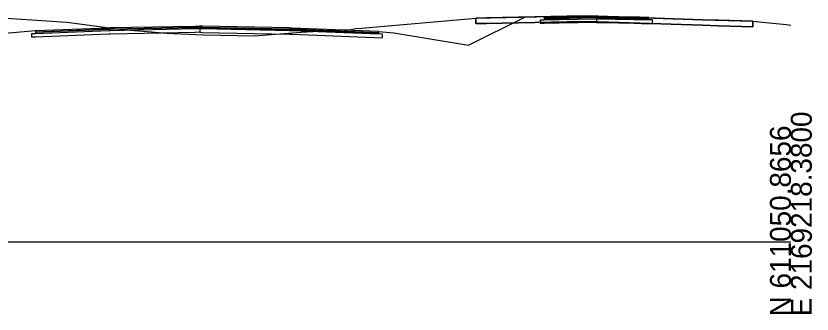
# Model space of a CAD drawing. Extents: x -26 to 1303, y -3010 to 12038.
# Drawn here: x 1196.2 to 1302.8, y 6990.3 to 7030.3 of the extents above; entities that cross this region are included whole.
import ezdxf

# ---------------------------------------------------------------- set-up
doc = ezdxf.new("R2010")
doc.units = 0
for name, color, linetype in [('RD_GPK_XS_Cell', 7, 'Continuous'), ('RD_XS_Base', 7, 'Continuous'), ('RD_XS_ExGround', 7, 'Continuous'), ('RD_XS_ExPaveRet', 7, 'Continuous'), ('RD_XS_Greenside', 7, 'Continuous'), ('RD_XS_Pave', 7, 'Continuous'), ('RD_XS_PaveOvlay_CP', 7, 'Continuous'), ('RD_XS_TieSlope', 7, 'Continuous')]:
    doc.layers.add(name, color=color, linetype=linetype)

msp = doc.modelspace()

# ---------------------------------------------------------------- linework, layer by layer
at = {"layer": 'RD_GPK_XS_Cell'}
msp.add_line((1150, 7000), (1300, 7000), dxfattribs=at)
at = {"layer": 'RD_XS_Base'}
for p, q in [((1266.47, 7029.77), (1266.97, 7029.78)), ((1266.47, 7029.27), (1266.47, 7029.77)), ((1266.97, 7029.78), (1268.97, 7029.82)), ((1268.97, 7029.82), (1273.97, 7029.92)), ((1273.97, 7029.42), (1268.97, 7029.32)), ((1273.97, 7029.99), (1273.97, 7030.08)), ((1273.97, 7030.08), (1273.97, 7029.7)), ((1273.97, 7029.92), (1273.97, 7029.99)), ((1276.91, 7029.86), (1273.97, 7029.92)), ((1273.97, 7029.92), (1273.97, 7029.42)), ((1273.97, 7029.7), (1273.97, 7029.42)), ((1273.97, 7029.42), (1276.91, 7029.36)), ((1278.97, 7029.82), (1276.91, 7029.86)), ((1279.78, 7029.8), (1278.97, 7029.82)), ((1280.97, 7029.78), (1279.78, 7029.8)), ((1281.17, 7029.77), (1280.97, 7029.78)), ((1281.47, 7029.77), (1281.17, 7029.77)), ((1281.47, 7029.47), (1281.47, 7029.77)), ((1281.47, 7029.27), (1281.47, 7029.47)), ((1198.81, 7027.97), (1208.65, 7028.36)), ((1208.65, 7028.36), (1208.81, 7028.37)), ((1208.81, 7028.37), (1220.21, 7028.6)), ((1220.21, 7028.6), (1220.81, 7028.61)), ((1220.81, 7028.76), (1220.81, 7028.77)), ((1220.81, 7028.77), (1220.81, 7028.75)), ((1220.81, 7028.61), (1220.81, 7028.76)), ((1220.81, 7028.75), (1220.81, 7028.11)), ((1220.81, 7028.61), (1220.81, 7028.6)), ((1220.81, 7028.61), (1220.81, 7028.61)), ((1221.12, 7028.6), (1220.81, 7028.61)), ((1220.81, 7028.61), (1220.81, 7028.61)), ((1220.81, 7028.6), (1220.81, 7028.11)), ((1232.81, 7028.37), (1221.12, 7028.6)), ((1233.17, 7028.35), (1232.81, 7028.37)), ((1244.81, 7027.89), (1233.17, 7028.35)), ((1266.97, 7029.28), (1266.47, 7029.27)), ((1268.97, 7029.32), (1266.97, 7029.28)), ((1276.91, 7029.36), (1278.97, 7029.32)), ((1278.97, 7029.32), (1279.98, 7029.3)), ((1279.98, 7029.3), (1281.47, 7029.27)), ((1198.31, 7027.95), (1198.81, 7027.97)), ((1198.31, 7027.94), (1198.31, 7027.95)), ((1198.31, 7027.45), (1198.31, 7027.94)), ((1198.81, 7027.47), (1198.31, 7027.45)), ((1198.81, 7027.97), (1198.81, 7027.97)), ((1208.65, 7027.86), (1198.81, 7027.47)), ((1198.81, 7027.47), (1198.81, 7027.47)), ((1208.81, 7027.87), (1208.65, 7027.86)), ((1220.21, 7028.1), (1208.81, 7027.87)), ((1220.81, 7028.11), (1220.21, 7028.1)), ((1220.81, 7028.11), (1221.12, 7028.1)), ((1221.12, 7028.1), (1232.81, 7027.87)), ((1232.81, 7027.87), (1233.19, 7027.85)), ((1233.19, 7027.85), (1245.31, 7027.37)), ((1244.83, 7027.89), (1244.81, 7027.89)), ((1245.31, 7027.87), (1244.83, 7027.89)), ((1245.31, 7027.85), (1245.31, 7027.87)), ((1245.31, 7027.37), (1245.31, 7027.85))]:
    msp.add_line(p, q, dxfattribs=at)
at = {"layer": 'RD_XS_ExGround'}
msp.add_lwpolyline([(1193.56, 7030.11), (1201.68, 7029.57), (1202.23, 7029.53), (1203.01, 7029.47), (1208.06, 7028.78), (1210.38, 7028.5), (1214.37, 7028.17), (1216.34, 7028), (1221.28, 7027.76), (1228.11, 7027.65), (1234.4, 7028.15), (1239.78, 7028.45), (1241.04, 7028.5), (1241.72, 7028.6), (1242.48, 7028.65), (1257.79, 7030.02), (1270, 7030.27), (1272.49, 7030.31), (1288.17, 7029.8), (1294.91, 7029.59), (1297.1, 7029.37), (1299.41, 7029.15), (1300, 7029.09)], dxfattribs=at)
at = {"layer": 'RD_XS_ExPaveRet'}
msp.add_line((1259.24, 7030.05), (1257.79, 7030.02), dxfattribs=at)
for points in [[(1294.91, 7029.59), (1294.91, 7029.59), (1294.91, 7029.45), (1294.91, 7028.84), (1294.91, 7028.84), (1294.91, 7028.84), (1290.29, 7028.99), (1288.17, 7029.05), (1274.19, 7029.51), (1272.49, 7029.56), (1270.69, 7029.53), (1270, 7029.52), (1259.24, 7029.3), (1257.79, 7029.27), (1257.79, 7029.92), (1257.79, 7030.02), (1259.24, 7030.05), (1270, 7030.27), (1270.69, 7030.28), (1272.49, 7030.31), (1274.19, 7030.26), (1288.17, 7029.8), (1290.29, 7029.74), (1294.91, 7029.59), (1294.91, 7029.59)], [(1257.79, 7030.02), (1257.79, 7029.92), (1257.79, 7029.27), (1259.24, 7029.3), (1270, 7029.52), (1270.69, 7029.53), (1272.49, 7029.56), (1274.19, 7029.51), (1288.17, 7029.05), (1290.29, 7028.99), (1294.91, 7028.84), (1294.91, 7028.84), (1294.91, 7029.45), (1294.91, 7029.59), (1294.91, 7029.59), (1290.29, 7029.74)], [(1270.69, 7030.28), (1270, 7030.27), (1259.24, 7030.05)], [(1274.19, 7030.26), (1272.49, 7030.31), (1270.69, 7030.28)], [(1290.29, 7029.74), (1288.17, 7029.8), (1274.19, 7030.26)]]:
    msp.add_lwpolyline(points, dxfattribs=at)
at = {"layer": 'RD_XS_Greenside'}
for p, q in [((1256.81, 7026.38), (1264.36, 7030.15)), ((1246.81, 7028.05), (1256.81, 7026.38))]:
    msp.add_line(p, q, dxfattribs=at)
at = {"layer": 'RD_XS_Pave'}
for p, q in [((1267.84, 7030.11), (1266.97, 7030.1)), ((1266.97, 7030.1), (1266.97, 7030.01)), ((1266.97, 7030.01), (1266.97, 7029.94)), ((1268.97, 7029.98), (1266.97, 7029.94)), ((1266.97, 7029.94), (1267.84, 7029.95)), ((1266.97, 7029.94), (1266.97, 7029.78)), ((1266.97, 7029.78), (1268.97, 7029.82)), ((1268.97, 7030.14), (1267.84, 7030.11)), ((1267.84, 7029.95), (1268.97, 7029.98)), ((1271.84, 7030.19), (1268.97, 7030.14)), ((1273.97, 7030.08), (1268.97, 7029.98)), ((1268.97, 7029.98), (1271.84, 7030.03)), ((1268.97, 7029.82), (1273.97, 7029.92)), ((1273.97, 7030.24), (1271.84, 7030.19)), ((1271.84, 7030.03), (1273.97, 7030.08)), ((1276.91, 7030.18), (1273.97, 7030.24)), ((1273.97, 7030.08), (1276.91, 7030.02)), ((1278.97, 7029.98), (1273.97, 7030.08)), ((1273.97, 7030.08), (1273.97, 7029.92)), ((1273.97, 7029.92), (1273.97, 7030.08)), ((1273.97, 7029.92), (1278.97, 7029.82)), ((1278.97, 7030.14), (1276.91, 7030.18)), ((1276.91, 7030.02), (1278.97, 7029.98)), ((1279.78, 7030.12), (1278.97, 7030.14)), ((1278.97, 7029.98), (1279.78, 7029.96)), ((1280.97, 7029.94), (1278.97, 7029.98)), ((1278.97, 7029.82), (1280.97, 7029.78)), ((1280.97, 7030.1), (1279.78, 7030.12)), ((1279.78, 7029.96), (1280.97, 7029.94)), ((1280.97, 7030), (1280.97, 7030.1)), ((1280.97, 7029.94), (1280.97, 7030)), ((1280.97, 7029.78), (1280.97, 7029.94)), ((1208.65, 7028.68), (1198.81, 7028.29)), ((1208.65, 7028.52), (1198.81, 7028.13)), ((1198.81, 7028.13), (1208.65, 7028.52)), ((1198.81, 7027.97), (1208.65, 7028.36)), ((1208.81, 7028.69), (1208.65, 7028.68)), ((1208.81, 7028.53), (1208.65, 7028.52)), ((1208.65, 7028.52), (1208.81, 7028.53)), ((1208.65, 7028.36), (1208.81, 7028.37)), ((1220.21, 7028.91), (1208.81, 7028.69)), ((1220.21, 7028.76), (1208.81, 7028.53)), ((1208.81, 7028.53), (1220.21, 7028.76)), ((1208.81, 7028.37), (1220.21, 7028.6)), ((1220.81, 7028.93), (1220.21, 7028.91)), ((1220.81, 7028.77), (1220.21, 7028.76)), ((1220.21, 7028.76), (1220.81, 7028.77)), ((1220.21, 7028.6), (1220.81, 7028.61)), ((1221.12, 7028.92), (1220.81, 7028.93)), ((1220.81, 7028.76), (1220.81, 7028.77)), ((1220.81, 7028.77), (1221.12, 7028.76)), ((1221.12, 7028.76), (1220.81, 7028.77)), ((1220.81, 7028.77), (1220.81, 7028.77)), ((1220.81, 7028.77), (1220.81, 7028.77)), ((1220.81, 7028.77), (1220.81, 7028.76)), ((1220.81, 7028.61), (1220.81, 7028.76)), ((1220.81, 7028.76), (1220.81, 7028.61)), ((1220.81, 7028.61), (1220.81, 7028.61)), ((1220.81, 7028.61), (1220.81, 7028.61)), ((1220.81, 7028.61), (1221.12, 7028.6)), ((1232.81, 7028.69), (1221.12, 7028.92)), ((1221.12, 7028.76), (1232.81, 7028.53)), ((1232.81, 7028.53), (1221.12, 7028.76)), ((1221.12, 7028.6), (1232.81, 7028.37)), ((1233.17, 7028.67), (1232.81, 7028.69)), ((1232.81, 7028.53), (1233.17, 7028.51)), ((1233.17, 7028.51), (1232.81, 7028.53)), ((1232.81, 7028.37), (1233.17, 7028.35)), ((1244.81, 7028.21), (1233.17, 7028.67)), ((1233.17, 7028.51), (1244.81, 7028.05)), ((1244.81, 7028.05), (1233.17, 7028.51)), ((1233.17, 7028.35), (1244.81, 7027.89)), ((1198.81, 7028.29), (1198.81, 7028.28)), ((1198.81, 7028.28), (1198.81, 7028.13)), ((1198.81, 7028.13), (1198.81, 7028.13)), ((1198.81, 7028.13), (1198.81, 7027.97)), ((1244.81, 7028.2), (1244.81, 7028.21)), ((1244.81, 7028.05), (1244.81, 7028.2)), ((1244.81, 7028.04), (1244.81, 7028.05)), ((1244.81, 7027.89), (1244.81, 7028.04))]:
    msp.add_line(p, q, dxfattribs=at)
at = {"layer": 'RD_XS_PaveOvlay_CP'}
for p, q in [((1266.97, 7030.1), (1268.97, 7030.14)), ((1268.97, 7030.14), (1273.97, 7030.24)), ((1273.97, 7030.24), (1278.97, 7030.14)), ((1278.97, 7030.14), (1280.97, 7030.1)), ((1208.65, 7028.68), (1198.81, 7028.29)), ((1208.81, 7028.69), (1208.65, 7028.68)), ((1220.21, 7028.91), (1208.81, 7028.69)), ((1220.81, 7028.93), (1220.21, 7028.91)), ((1221.12, 7028.92), (1220.81, 7028.93)), ((1232.81, 7028.69), (1221.12, 7028.92)), ((1233.17, 7028.67), (1232.81, 7028.69)), ((1244.81, 7028.21), (1233.17, 7028.67))]:
    msp.add_line(p, q, dxfattribs=at)
at = {"layer": 'RD_XS_TieSlope'}
for p, q in [((1198.81, 7028.29), (1192.81, 7027.81)), ((1244.81, 7028.21), (1246.81, 7028.05))]:
    msp.add_line(p, q, dxfattribs=at)

# ---------------------------------------------------------------- texts
at = {"layer": 'RD_GPK_XS_Cell'}
for s, p in [('E 2169218.3800', (1302.8, 6990)), ('N 611050.8656', (1300, 6990))]:
    msp.add_text(s, height=2.8, rotation=90, dxfattribs=at).set_placement(p)

doc.saveas('drawing.dxf')
